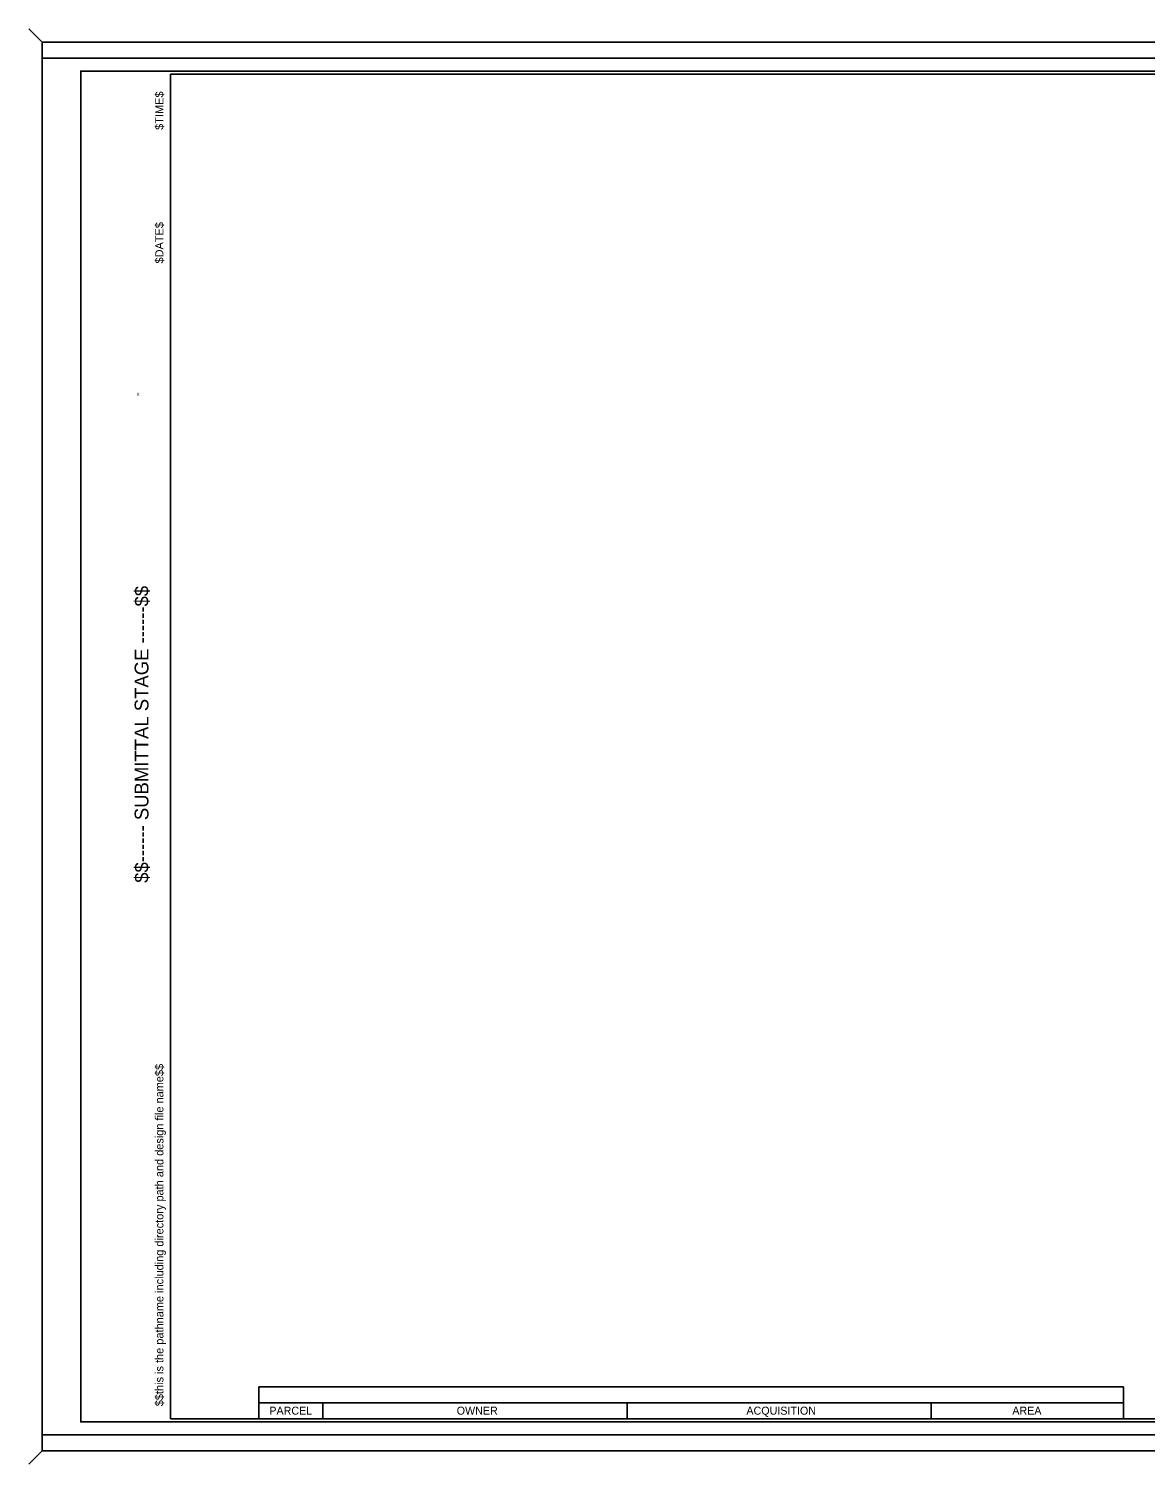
# Model space of a CAD drawing. Extents: x -2.5 to 31.7, y -0.7 to 21.7.
# Drawn here: x -2.51 to 14.92, y -0.71 to 21.71 of the extents above; entities that cross this region are included whole.
import ezdxf

# ---------------------------------------------------------------- set-up
doc = ezdxf.new("R2010")
doc.units = 0
for name, color, linetype in [('Border Sheet Acquisition Data', 7, 'Continuous'), ('Construction Class', 7, 'Continuous'), ('Plot Border', 7, 'Continuous'), ('Plot Border 2', 7, 'Continuous'), ('Sheet Border', 7, 'Continuous')]:
    doc.layers.add(name, color=color, linetype=linetype)

msp = doc.modelspace()

# ---------------------------------------------------------------- linework, layer by layer
at = {"layer": 'Border Sheet Acquisition Data'}
for p, q in [((1.08, 0.5), (14.58, 0.5)), ((1.08, 0.5), (1.08, 0)), ((14.58, 0.5), (14.58, 0)), ((1.08, 0.25), (14.58, 0.25)), ((2.08, 0.25), (2.08, 0)), ((6.83, 0.25), (6.83, 0)), ((11.58, 0.25), (11.58, 0))]:
    msp.add_line(p, q, dxfattribs=at)
at = {"layer": 'Construction Class'}
msp.add_line((-0.8, 16), (-0.8, 16), dxfattribs=at)
at = {"layer": 'Plot Border'}
for p, q in [((-2.3, 21.5), (-2.512, 21.712)), ((-2.3, -0.5), (-2.512, -0.712))]:
    msp.add_line(p, q, dxfattribs=at)
for points in [[(-2.3, 21.5), (31.7, 21.5), (31.7, -0.5), (-2.3, -0.5)], [(31.3, 21.05), (-1.7, 21.05), (-1.7, -0.05), (31.3, -0.05)]]:
    msp.add_lwpolyline(points, close=True, dxfattribs=at)
at = {"layer": 'Plot Border 2'}
msp.add_lwpolyline([(-2.3, 21.25), (31.7, 21.25), (31.7, -0.25), (-2.3, -0.25)], close=True, dxfattribs=at)
at = {"layer": 'Sheet Border'}
for p, q in [((31.2, 21), (-0.3, 21)), ((-0.3, 21), (-0.3, 0)), ((-0.3, 0), (31.2, 0))]:
    msp.add_line(p, q, dxfattribs=at)

# ---------------------------------------------------------------- texts
at = {"layer": 'Border Sheet Acquisition Data'}
for s, p in [('PARCEL', (1.245, 0.063)), ('OWNER', (4.171, 0.063)), ('ACQUISITION', (8.694, 0.063)), ('AREA', (12.846, 0.063))]:
    msp.add_text(s, height=0.125, dxfattribs=at).set_placement(p)
at = {"layer": 'Plot Border'}
for s, height, p in [('$TIME$', 0.128, (-0.409, 20.133)), ('$DATE$', 0.128, (-0.409, 18.045)), ('$$------ SUBMITTAL STAGE ------$$', 0.216, (-0.642, 8.371)), ('$$this is the pathname including directory path and design file name$$', 0.128, (-0.409, 0.195))]:
    msp.add_text(s, height=height, rotation=90, dxfattribs=at).set_placement(p)
at = {"layer": 'Sheet Border'}
msp.add_text('X', height=0.05, dxfattribs=at).set_placement((-0.827, 15.975))

doc.saveas('drawing.dxf')
